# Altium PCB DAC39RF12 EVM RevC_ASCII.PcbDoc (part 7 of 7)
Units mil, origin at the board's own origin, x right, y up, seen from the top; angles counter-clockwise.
Board outline 5071.81 x 2716.54 mil, 16 copper layers (Top Layer, L2 GND1, L3 PWR1, L4 GND2, L5 PWR2, L6 GND3, L7 Ctrl Signal 1, L8 GND4, L9 GND5, L10 Ctrl Signal 2, L11 GND6, L12 PWR3, L13 GND7, L14 PWR4, L15 GND8, Bottom Layer), stack 82.4 mil thick; 596 components, 375 nets, 3310 pads, 1662 vias.
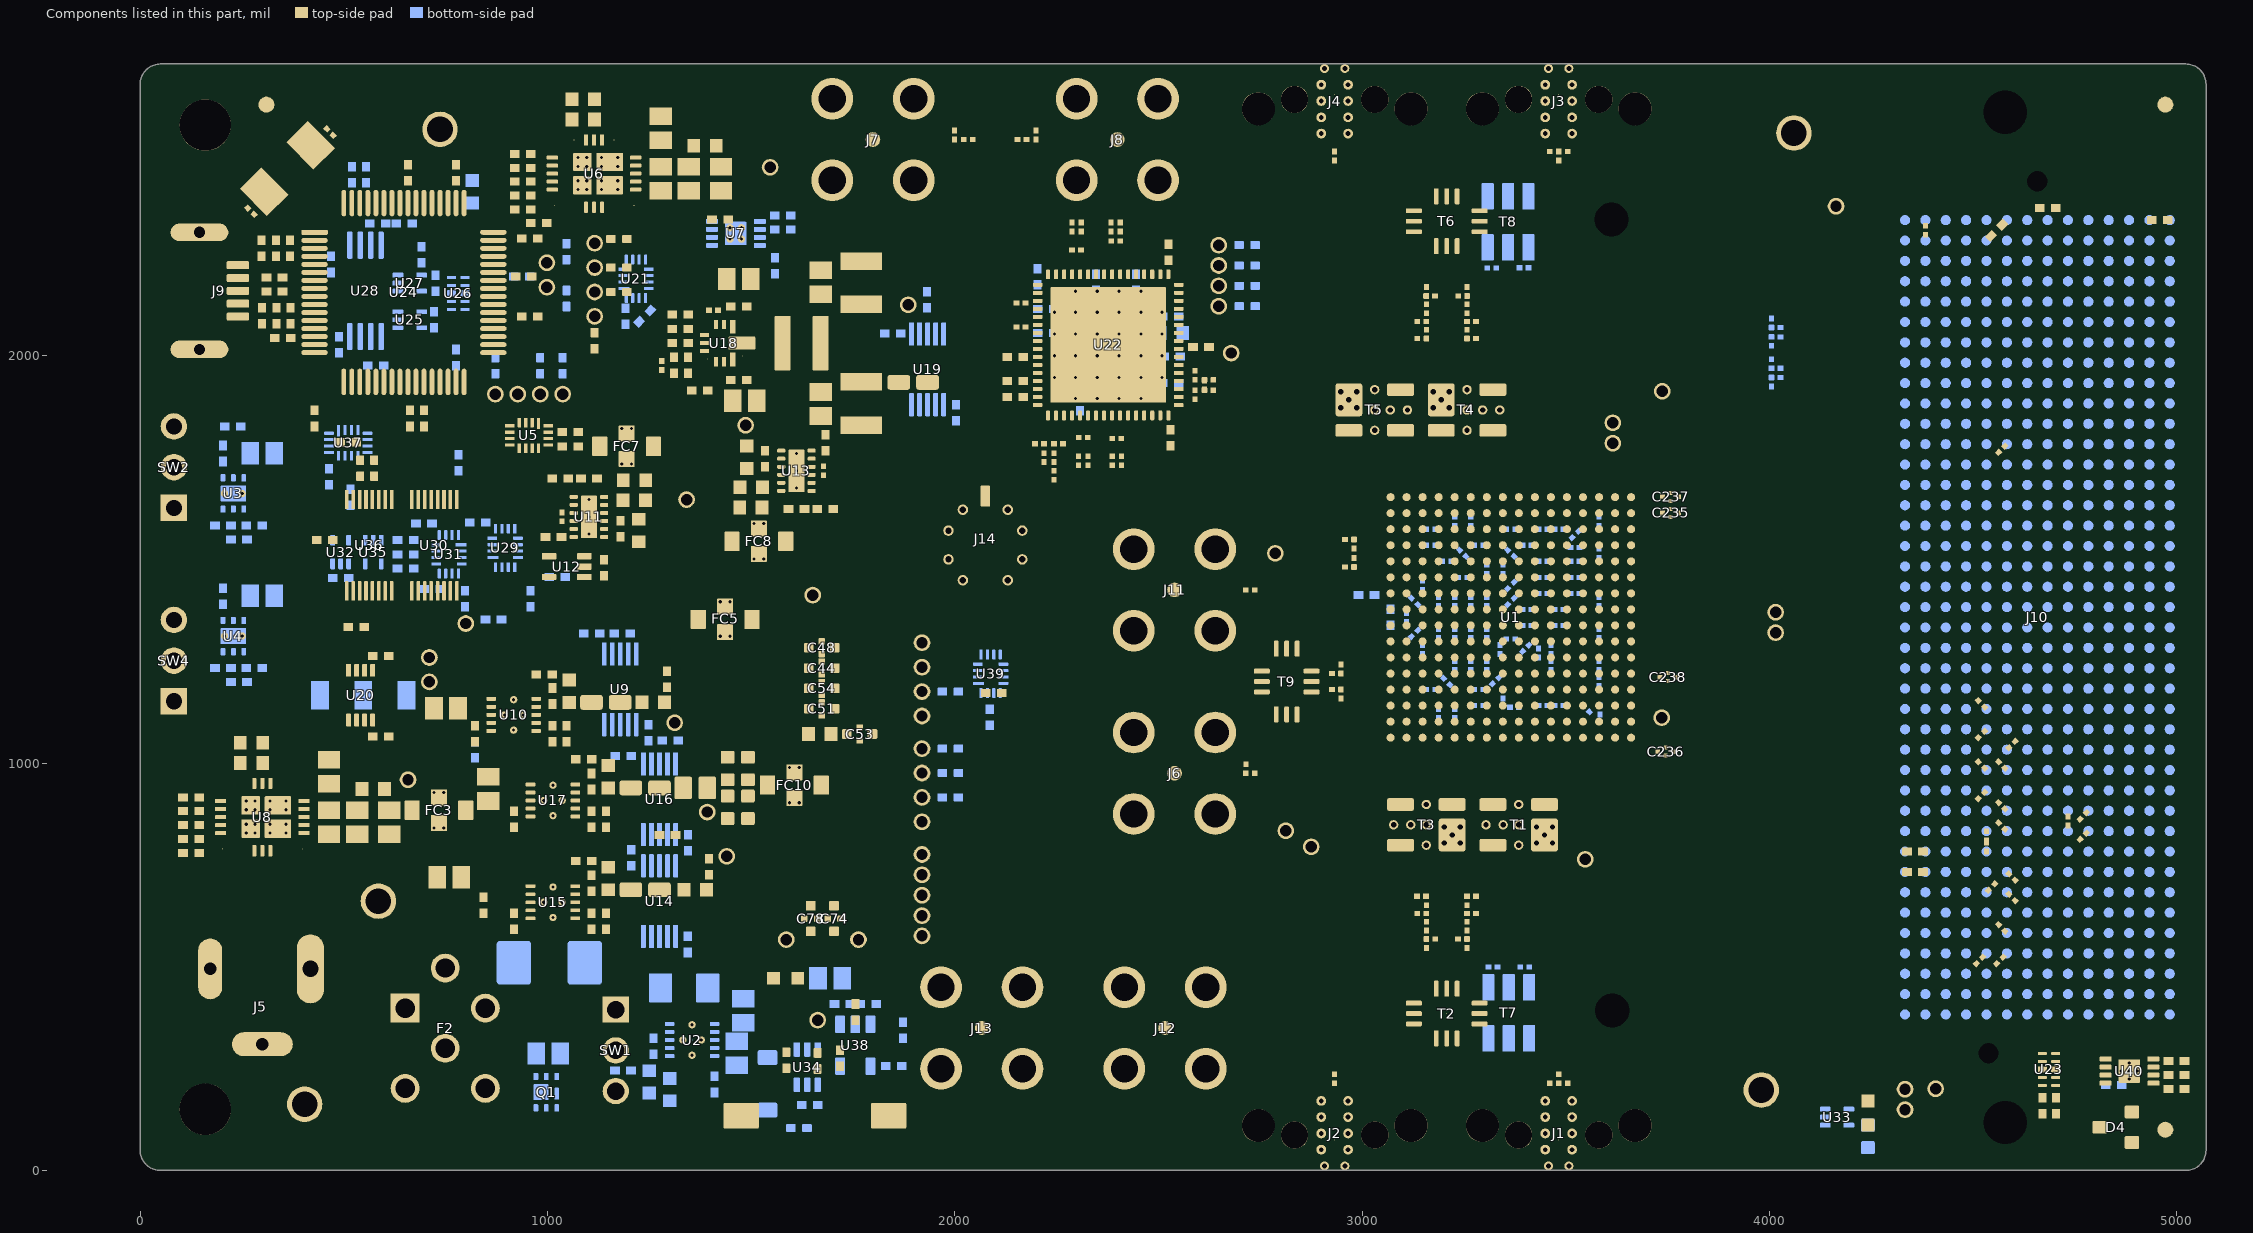
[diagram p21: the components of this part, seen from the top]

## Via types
v1: diameter 18, hole 8, Top Layer to Bottom Layer, tented both sides, 1558 vias
v2: diameter 20, hole 10, Top Layer to Bottom Layer, tented both sides, 92 vias
v3: diameter 27, hole 15, Top Layer to Bottom Layer, tented both sides, 12 vias

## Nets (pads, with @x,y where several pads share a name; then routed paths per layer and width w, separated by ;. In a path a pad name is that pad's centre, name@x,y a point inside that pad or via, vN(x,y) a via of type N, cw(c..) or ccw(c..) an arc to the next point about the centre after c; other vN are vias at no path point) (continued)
pads on no net: "U6. "@1016.37,2525.57 FID1.1 FID2.1 FID3.1 H3. H4. H5.1 H6.1 J6.5 J9.1 J9.4 J10. J10.A2 J10.A3 J10.A6 J10.A7 J10.A10 J10.A11 J10.A14 J10.A15 J10.A18 J10.A19 J10.B1 J10.B4 J10.B5 J10.B8 J10.B9 J10.B12 J10.B13 J10.B16 J10.B17 J10.B40 J10.C6 J10.C7 J10.C10 J10.C11 J10.C14 J10.C15 J10.C16 J10.C18 J10.C19 J10.D8 J10.D9 J10.D11 J10.D12 J10.D14 J10.D15 J10.D16 J10.D17 J10.D18 J10.D20 J10.D21 J10.D29 J10.D33 J10.D34 J10.E2 J10.E3 J10.E6 J10.E7 J10.E9 J10.E10 J10.E12 J10.E13 J10.E15 J10.E16 J10.E17 J10.E18 J10.E19 J10.E21 J10.E22 J10.E24 J10.E25 J10.E27 J10.E28 J10.E30 J10.E31 J10.E33 J10.E34 J10.E36 J10.E37 J10.F4 J10.F5 J10.F7 J10.F8 J10.F10 J10.F11 J10.F13 J10.F14 J10.F15 J10.F16 J10.F17 J10.F18 J10.F19 J10.F20 J10.F22 J10.F23 J10.F25 J10.F26 J10.F28 J10.F29 J10.F31 J10.F32 J10.F34 J10.F35 J10.F37 J10.F38 J10.G2 J10.G3 J10.G15 J10.G16 J10.G17 J10.G18 J10.G19 J10.G21 J10.G22 J10.G24 J10.G25 J10.H1 J10.H4 J10.H5 J10.H7 J10.H8 J10.H10 J10.H11 J10.H13 J10.H14 J10.H15 J10.H16 J10.H17 J10.H19 J10.H20 J10.H22 J10.H23 J10.H35 J10.J2 J10.J3 J10.J4 J10.J5 J10.J6 J10.J7 J10.J9 J10.J10 J10.J12 J10.J13 J10.J15 J10.J16 J10.J17 J10.J18 J10.J19 J10.J21 J10.J22 J10.J24 J10.J25 J10.J27 J10.J28 J10.J30 J10.J31 J10.J33 J10.J34 J10.J36 J10.J37 J10.J39 J10.K1 J10.K2 J10.K3 J10.K4 J10.K5 J10.K7 J10.K8 J10.K10 J10.K11 J10.K12 J10.K13 J10.K14 J10.K15 J10.K16 J10.K17 J10.K19 J10.K20 J10.K22 J10.K23 J10.K25 J10.K26 J10.K28 J10.K29 J10.K31 J10.K32 J10.K34 J10.K35 J10.K37 J10.K38 J10.K40 J10.L3 J10.L4 J10.L5 J10.L7 J10.L8 J10.L9 J10.L10 J10.L12 J10.L13 J10.L15 J10.L16 J10.L17 J10.L19 J10.L20 J10.L21 J10.L24 J10.L25 J10.L28 J10.L29 J10.M2 J10.M3 J10.M4 J10.M5 J10.M6 J10.M7 J10.M10 J10.M11 J10.M12 J10.M14 J10.M15 J10.M17 J10.M18 J10.M19 J10.M20 J10.M22 J10.M23 J10.M26 J10.M27 J10.M30 J10.M31 J10.M34 J10.M35 J10.M38 J10.M39 J10.Y2 J10.Y3 J10.Y10 J10.Y11 J10.Y14 J10.Y15 J10.Y34 J10.Y35 J10.Y38 J10.Y39 J10.Z4 J10.Z5 J10.Z12 J10.Z13 J10.Z16 J10.Z17 J10.Z20 J10.Z21 J10.Z32 J10.Z33 J10.Z36 J10.Z37 J11.5 J12.5 J13.5 LBL1.0 Q1.0 T1.4 T3.4 T4.4 T5.4 U2.9 U3.3 U3.7@211.25,1662.04 U3.7@246.68,1662.04 U4.3 U4.7@211.25,1312.04 U4.7@246.68,1312.04 U6.4 U8.4 U9.3 U11.2 U11.11 U12.1 U13.1 U13.2 U13.11 U14.3 U16.3 U19.3 U22.1 U22.2 U22.7 U22.8 U22.9 U22.13 U22.14 U22.15 U22.16 U22.22 U22.23 U22.29 U22.30 U22.31 U22.32 U22.40 U22.41 U22.43 U22.44 U22.46 U22.48 U22.49 U22.50 U22.59 U22.60 U22.61 U22.62 U22.63 U23.3@4669.81,247.98 U23.8@4702.69,247.98 U24.21 U24.22 U24.23 U24.24 U24.29 U24.30 U24.32 U24.33 U24.34 U24.36 U24.55 U24.57 U24.58 U24.59 U24.60 U26.3@764.51,2153.25 U26.8@797.38,2153.25 U28.6 U28.7 U29.4 U29.9 U39.4 U39.6 U39.9

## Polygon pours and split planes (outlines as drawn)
GND on L5 PWR2 "L5_PWR2_GND_P081" (solid, remove dead copper, pour order 81): 10,0 5071.81,0 5071.81,2716.54 10,2716.54
VDDLB on L5 PWR2 "L5 PWR2-VDDLB" (solid, remove dead copper, pour order 79): 1384.73,0 4571.81,0 4571.81,2327.76 3294.03,2327.76 3294.03,1360 3839.92,1360 3839.92,415 1681.3,415 1681.3,627.38 1384.73,627.38
VDDCLK10 on L5 PWR2 "L5 PWR2-VDDCLK10" (solid, pour order 44): 483.65,896.46 3179.62,896.46 3179.62,1132.95 3278.98,1232.32 3278.98,1484.8 3190.99,1572.79 3190.99,2329.24 483.65,2329.24
VDDLA on L5 PWR2 "L5_PWR2_VDDLA_P075" (solid, pour order 75): 1681.68,415 3839.92,415 3839.92,1349.14 3294.03,1349.14 3294.03,752.36 1681.68,752.36
GND on L10 Ctrl Signal 2 "L10_CTRL_SIGNAL_2_GND_P177" (solid, remove dead copper, pour order 177): 10,0 5071.81,0 5071.81,2716.54 10,2716.54
VDD_FPGA on L10 Ctrl Signal 2 "L10 Ctrl Signal 2-VDD_FPGA" (solid, pour order 168): 993.77,1760.42 1364.46,1760.42 1364.46,2262.22 1170.34,2262.22 1170.34,2077.47 1051.73,2077.47 1051.73,1858.95 993.77,1858.95
GND on L12 PWR3 "L12_PWR3_GND_P181" (solid, remove dead copper, pour order 181): 10,0 5071.81,0 5071.81,2716.54 10,2716.54
VADJ_FMC on L12 PWR3 "L12 PWR3-VADJ_FMC" (solid, pour order 173): 4718.81,0 4718.81,705.91 2091.18,705.91 2091.18,186.96 410,186.96 410,1210 0,1210 0,0 2091.18,0
VEExA on L12 PWR3 "L12 PWR3-VEExA" (solid, pour order 167): 1252.77,1628.99 2882.03,1628.99 2882.03,1931.86 3832.81,1931.86 3832.81,1219.99 3148.55,1219.99 3148.55,952.06 4571.81,952.06 4571.81,2716.54 2060,2716.54 2060,1845 1520.93,1845 1520.93,1956.81 1252.77,1956.81
VDDA18A on L12 PWR3 "L12 PWR3-VDDA18A" (solid, pour order 162): 1896.85,921.63 1896.85,706.97 3511.53,706.97 3511.53,950 3149.12,950 3147.55,1219.99 3832.81,1219.99 3832.81,1352.31 3041.46,1352.31 3041.46,1252.96 1681.23,1252.96 1681.23,921.63
VEExB on L12 PWR3 "L12 PWR3-VEExB" (solid, pour order 160): 1252.77,1432.97 2908.82,1432.97 2908.82,1477.87 3345.4,1477.87 3345.4,1613.69 1353.36,1613.69 1353.36,1685.58 1252.77,1685.58 1252.77,1491.34
VDDA18B on L12 PWR3 "L12 PWR3-VDDA18B" (solid, pour order 165): 1680.32,1252.96 3041.46,1252.96 3041.46,1352.31 3832.81,1352.31 3832.81,1931.86 2882.03,1931.86 2882.03,1613.69 3345.4,1613.69 3345.4,1477.87 2908.82,1477.87 2908.82,1401.04 1680.32,1401.04
VDDIO on L12 PWR3 "L12 PWR3-VDDIO" (solid, pour order 171): 410,186.96 2091.18,186.96 2091.18,479.32 1252.77,479.32 1252.77,1932 410,1932 410,1470.29 25.49,1470.52 25.49,1299.81 410,1299.81
VDD_FPGA on L12 PWR3 "L12 PWR3-VDD_FPGA" (solid, pour order 156): 27,1210 1020.86,1210 1020.86,1437.02 1075.46,1437.02 1075.46,1799.59 746.4,1799.59 746.4,1431.71 631.8,1431.71 631.8,1300.11 25.49,1300.11 27,1299.81
3p3V_Utility on L12 PWR3 "L12 PWR3-3p3V_Utility" (solid, remove dead copper, pour order 170): 10,1470.52 407.23,1470.52 407.23,1932 1106.71,1932 1252.77,1932 1252.77,1956.81 1520.93,1956.81 1520.93,1845 2057.94,1845 2057.94,2716.54 10,2716.54
3P3VAUX-FMC on L12 PWR3 "L12 PWR3-3P3VAUX-FMC" (solid, pour order 130): 4550,0 4678.13,0 4678.13,295 4865,295 4865,0 5071.81,0 5071.81,853.18 4505,853.18 4505,720 4720.81,720 4720.81,345 4550,345
3p3V_EEPROM on L12 PWR3 "L12_PWR3_3P3V_EEPROM_P133" (solid, pour order 133): 4678.13,295 4678.13,0 4865,0 4865,295 4860,295
GND on L3 PWR1 "L3_PWR1_GND_P175" (solid, remove dead copper, pour order 175): 10,0 5071.81,0 5071.81,2716.54 10,2716.54
3p3V_Clock on L3 PWR1 "L3 PWR1-3p3V_Clock" (solid, pour order 153): 1906.07,1790.96 3030.83,1790.96 3030.83,2716.54 1440.65,2716.54 1440.65,1923.45 1906.07,1923.45
DVDD on L3 PWR1 "L3 PWR1-DVDD" (solid, remove dead copper, pour order 137): 1440.65,359.67 5071.81,359.67 5071.81,2716.54 3030.83,2716.54 3030.83,1790.96 1896.85,1790.96 1896.85,1920.87 1440.65,1920.87
3p3V_Utility on L3 PWR1 "L3 PWR1-3p3V_Utility" (solid, pour order 120): 10,0 5071.81,0 5071.81,359.67 1440.2,359.67 1440.2,1262.21 1103.21,1262.21 1103.21,1435.28 1163.9,1435.28 1163.9,1912.63 10,1912.63
12V on L3 PWR1 "NONET_L10_P-001" (solid, pour order 30): 222.99,986.84 657.49,986.84 657.49,1240.02 222.99,1240.02 222.99,986.56
VDDIO on L3 PWR1 "NONET_L10_P-001" (solid, pour order 139): 1103.21,1435.28 1103.21,1262.21 1441.26,1262.21 1441.26,2210 1166.34,2210 1166.34,1435.28
VCORE on L3 PWR1 "NONET_L10_P-001" (solid, pour order 151): 433.62,2415.74 433.62,2041.74 889.65,2041.74 889.65,2415.74
GND on L2 GND1 "L2_GND1_GND_P028" (solid, remove dead copper, pour order 28): 0,0 5071.81,0 5071.81,2716.54 0,2716.54
GND on L14 PWR4 "L14_PWR4_GND_P157" (solid, remove dead copper, pour order 157): 10,0 5071.81,0 5071.81,2716.54 10,2716.54
12V_FMC on L14 PWR4 "L14 PWR4-12V_FMC" (solid, remove dead copper, pour order 145): 465.8,0 5071.81,0.82 5071.81,665 3787,665 3787,465 1590,465 1590,262.71 465.8,262.71
VDDIO on L14 PWR4 "L14 PWR4-VDDIO" (solid, pour order 132): 3447.76,739.03 3447.76,1241.53 2850.8,1241.53 2850.8,865 1680.2,865 1680.2,1412.75 1542.02,1412.75 1542.02,1334.94 1168.01,1334.94 1168.01,1437.02 1166.34,1437.02 1020.86,1437.02 1020.86,739.03
VDDCLK18 on L14 PWR4 "L14 PWR4-VDDCLK18" (solid, pour order 143): 3487.82,1047.89 3800,1047.89 3800,1160.81 3685,1160.81 3685,1365.43 2492.76,1365.43 2492.76,1029.34 1793.53,1029.34 1793.51,1030.82 1793.51,1162.48 1680.2,1162.48 1680.2,864.59 2850.32,864.59 2850.32,1241.53 3487.82,1241.53 3487.82,1144.71
VDDSYS18 on L14 PWR4 "L14_PWR4_VDDSYS18_P102" (solid, pour order 102): 3266.66,1365.43 3266.66,1546.64 1909.73,1546.64 1909.73,1142.11 1793.51,1142.11 1793.51,1030.82 2492.76,1030.82 2492.76,1365.43
VDDR on L14 PWR4 "L14_PWR4_VDDR_P116" (solid, pour order 116): 1909.73,1164.8 1909.73,1546.64 3266.66,1546.64 3266.66,1365.43 3882.81,1365.43 3882.81,1900.62 1680.2,1900.62 1680.2,1164.8
12V on L14 PWR4 "L14 PWR4-12V" (solid, pour order 123): 10,0 465.8,0 465.8,264.63 1590,264.63 1590,569.7 678.2,569.7 678.2,1808.29 1520.93,1808.29 1520.93,2295.21 1107.23,2295.21 1107.23,2396.66 848.92,2396.66 848.92,2551.45 1108.69,2551.45 1108.69,2716.54 10,2716.54
fanPwr on L14 PWR4 "L14 PWR4-fanPwr" (solid, pour order 101): 1701.5,528 3718.17,528 3718.17,804.72 4062.49,804.72 4062.49,1365.43 3718.17,1365.43 3718.17,1248.06 3841.46,1248.06 3841.46,956.91 3553.55,956.91 3553.55,724.33 934.37,724.33 934.37,1227.31 496.42,1227.31 496.42,1075.78 756.51,1075.78 756.51,603.37 1701.5,603.37
3p3V_Clock on L14 PWR4 "NONET_L10_P-001" (solid, pour order 129): 1225.36,1560.77 1683.75,1560.77 1683.75,2716.54 1108.69,2716.54 1108.69,2551.45 848.92,2551.45 848.92,2396.66 1107.23,2396.66 1107.23,2295.21 1520.93,2295.21 1520.93,1808.29 1225.36,1808.29
GND on L4 GND2 "L4_GND2_GND_P043" (solid, remove dead copper, pour order 43): 10,0 5071.81,0 5071.81,2716.54 10,2716.54
GND on L7 Ctrl Signal 1 "L7_CTRL_SIGNAL_1_GND_P182" (solid, remove dead copper, pour order 182): 10,0 5071.81,0 5071.81,2716.54 10,2716.54
VDD_FPGA on L7 Ctrl Signal 1 "gnd" (solid, pour order 154): 1310,1850 2130.12,1850 2130.12,1158.43 1784.05,1158.43 1784.05,1598.91 1310,1598.91
VDDIO on L7 Ctrl Signal 1 "gnd" (solid, pour order 178): 2130.12,1158.43 2130.12,1065 1580,1065 1580,1460 1785,1460 1785,1160 2130,1160
GND on L6 GND3 "L6_GND3_GND_P045" (solid, remove dead copper, pour order 45): 10,0 5071.81,0 5071.81,2716.54 10,2716.54
GND on L8 GND4 "L8_GND4_GND_P048" (solid, remove dead copper, pour order 48): 10,0 5071.81,0 5071.81,2716.54 10,2716.54
GND on L9 GND5 "L9_GND5_GND_P049" (solid, remove dead copper, pour order 49): 10,0 5071.81,0 5071.81,2716.54 10,2716.54
GND on L11 GND6 "L11_GND6_GND_P051" (solid, remove dead copper, pour order 51): 10,0 5071.81,0 5071.81,2716.54 10,2716.54
GND on L13 GND7 "L13_GND7_GND_P053" (solid, remove dead copper, pour order 53): 10,0 5071.81,0 5071.81,2716.54 10,2716.54
GND on L15 GND8 "L15_GND8_GND_P054" (solid, remove dead copper, pour order 54): 10,0 5071.81,0 5071.81,2716.54 10,2716.54
GND on Bottom Layer "BOTTOM_LAYER_GND_P158" (solid, remove dead copper, pour order 158): 10,0 5071.81,0 5071.81,2716.54 10,2716.54
GND on Top Layer "TOP_LAYER_GND_P183" (solid, remove dead copper, pour order 183): 0,0 5071.81,0 5071.81,2716.54 0,2716.54

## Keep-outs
Keep-Out Layer:
  text ".Layer_Name" at 587,-858.49 h60

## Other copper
Top Layer:
  text ".Layer_Name" at 579.82,-843.49 h60
L2 GND1:
  text ".Layer_Name" at 579.82,-843.49 h60
L3 PWR1:
  text ".Layer_Name" at 579.82,-843.49 h60
L4 GND2:
  text ".Layer_Name" at 579.82,-843.49 h60
L5 PWR2:
  text "PWR2" at 579.82,-843.49 h60
L6 GND3:
  text ".Layer_Name" at 579.82,-843.49 h60
L11 GND6:
  text ".Layer_Name" at 579.82,-843.49 h60
L12 PWR3:
  text ".Layer_Name" at 579.82,-843.49 h60
L13 GND7:
  text ".Layer_Name" at 579.82,-843.49 h60
L14 PWR4:
  text ".Layer_Name" at 579.82,-843.49 h60
L15 GND8:
  text ".Layer_Name" at 579.82,-843.49 h60
L7 Ctrl Signal 1:
  text ".Layer_Name" at 579.82,-843.49 h60
L10 Ctrl Signal 2:
  text ".Layer_Name" at 579.82,-843.49 h60
L8 GND4:
  text ".Layer_Name" at 579.82,-843.49 h60
L9 GND5:
  text ".Layer_Name" at 579.82,-843.49 h60
Bottom Layer:
  text ".Layer_Name" at 579.82,-843.49 h60

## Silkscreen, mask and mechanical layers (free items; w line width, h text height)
Top Overlay:
  lines w5: 145,2335 255,2335 280,2310 ; 260,2310 280,2310 ; 639.26,1177.37 639.26,1287.11 ; 280,2310 280,2330 280,2310 ; 25,2335 150,2335 150,2450 25,2450 25,2335
  lines w7: 1505,220 1505,410 ; 1695,345 1695,490 ; 1953.61,1143.1 2005.97,1143.16 ; 1954.4,881.95 2006.76,882.01 ; 2069.92,597.86 2123.63,597.97 ; 2071.27,797.97 2123.63,798.03 ; 2540.71,984.9 2540.71,1034.9 ; 2683.86,2298.35 2733.86,2298.35
  text "LMK" at 2614,2161 h30 r90
  text "DAC39RF12EVM / RevC   DC296" at 3791.14,1855.95 h60
  text "SYNC" at 678.53,1175.95 h30 r90
  text "USB2FMC" at 1889,1111 h30 r90
  text "DAC SPI" at 1889,851 h30 r90
  text "FMC SPI" at 1889,571 h30 r90
  text ".Layer_Name" at 579.82,-843.49 h60
Bottom Overlay:
  lines w7: 895,1835 895,1885 ; 1535,430 1672.65,431.76 ; 1830,1140 1880,1140 ; 1840,880 1890,880 ; 1950,600 2000,600 ; 1950,800 2000,800 ; 2050,1141.48 2100,1141.48 ; 2570,2295 2620,2295 ; 2585,1095 2585,1145 ; 2845,965 2845,1015 ; 3095,1325 3115,1325 3145,1355 3605,1355 3645,1355 ; 3105,1325 3090,1325 ; 3090,1325 3090,995 3015,920 3015,620 3465,620 3495,620 3500,620 3500,510 3645,510 3645,1355 ; 3090,1325 3090,1625 2985,1625 2985,2082.06 3645,2082.06 3645,1355
  text "DAC" at 1756,886 h30 r270
  text "LMX" at 2899,876 h30
  text "FMC" at 1851,641 h30 r270
  text ".Layer_Name" at 587,-858.49 h60
Top Paste:
  text ".Layer_Name" at 587,-858.49 h60
Bottom Paste:
  text ".Layer_Name" at 593.41,-871.99 h60
Top Solder:
  text ".Layer_Name" at 587,-858.49 h60
  text ".Layer_Name" at 587,-858.49 h60
Bottom Solder:
  rectangle: 2967.44,1192.08 2975.94,1208.5
  text ".Layer_Name" at 593.41,-871.99 h60
Drill Guide:
  text ".Layer_Name" at 417,-408.49 h60
M1 Board Outline:
  lines w10: 0,50 ccw(c50,50) 50,0 110,0 4970,0 5021.81,0 ccw(c5021.81,50) 5071.81,50 5071.81,100 5071.81,2616.53 5071.81,2666.54 ccw(c5021.81,2666.54) 5021.81,2716.54 4970,2716.54 100,2716.54 50,2716.54 ccw(c50,2666.54) 0,2666.54 0,2616.53 0,100 0,50
  text ".Layer_Name" at 587,-858.49 h60
M2 Board Dimensions:
  rectangle: 135,-400 510,-275
  rectangle: 10,-275 135,-150
  lines w7: 10,-275 1010,-275 ; 10,-150 10,-400 1010,-400 1010,-150 ; 135,-400 135,-150 ; 260,-400 260,-150 ; 510,-400 510,-150 ; 760,-400 760,-150
  text ".Layer_Name" at 587,-858.49 h60
M3 3D STEP Top:
  text ".Layer_Name" at 587,-858.49 h60
M4 3D STEP Bottom:
  text ".Layer_Name" at 593.41,-871.99 h60
M5 Assembly Top:
  lines w10: -282,-930.17 6318,-930.17 ; -282,-726.83 6320,-726.83 ; -282,-523.5 -282,-1133.5 3723,-1133.5 6320,-1133.5 6320,-523.5 -281.5,-523.5 -281.5,-1133.5 1294,-1133.5 ; 2183,-1133.5 2183,-523.5 ; 3450,-726.83 3450,-523.5 ; 4290,-726.83 4290,-523.5 ; 4912,-1140 4912,-937.17
  text "COMPONENTS MARKED 'DNP' SHOULD NOT BE POPULATED." at 1163.5,-318.5 h60
  text "ASSEMBLY VARIANT:" at 1163,-434 h60
  text ".VariantName" at 2199,-434 h60
  text "PCB VIEWED FROM TOP SIDE" at -218.5,-655.67 h60
  text "BOARD #:" at 2258,-655.67 h60
  text ".PRJ_Number" at 2803.5,-655.67 h60
  text "REV:" at 3648,-655.67 h60
  text ".PCB_Rev" at 3939.5,-655.67 h60
  text "SVN REV:" at 4486,-655.67 h60
  text ".VersionControl_RevNumber" at 4992,-655.67 h60
  text "PLOT NAME =" at -218.5,-1064.34 h60
  text ".plot_File_Name" at 587,-1064.34 h60
  text "GENERATED    :" at 2260,-1064.34 h60
  text ".Print_Date" at 3129.5,-1064.34 h60
  text ".Print_Time" at 3858.5,-1064.34 h60
  text "TEXAS INSTRUMENTS" at 5123,-1064.34 h60
M6 Assembly Bottom:
  lines w10: -282.5,-727.33 6319.5,-727.33 ; -280.5,-930.67 6319.5,-930.67 ; 1125.5,-1140.5 1125.5,-937.67 ; 1747.5,-727.33 1747.5,-524 ; 2587.5,-727.33 2587.5,-524 ; 3854.5,-1134 3854.5,-524 ; 4743.5,-1134 6319,-1134 6319,-524 -282.5,-524 -282.5,-1134 2314.5,-1134 6319.5,-1134 6319.5,-524
  text "COMPONENTS MARKED 'DNP' SHOULD NOT BE POPULATED." at 6112,-318 h60
  text ".VariantName" at 5068,-434 h60
  text "ASSEMBLY VARIANT:" at 6107,-434 h60
  text ".VersionControl_RevNumber" at 1045.5,-656.17 h60
  text "SVN REV:" at 1551.5,-656.17 h60
  text ".PCB_Rev" at 2098,-656.17 h60
  text "REV:" at 2389.5,-656.17 h60
  text ".PRJ_Number" at 3234,-656.17 h60
  text "BOARD #:" at 3779.5,-656.17 h60
  text "PCB VIEWED FROM BOTTOM SIDE" at 6256,-656.17 h60
  text "TEXAS INSTRUMENTS" at 914.5,-1064.84 h60
  text ".Print_Time" at 2179,-1064.84 h60
  text ".Print_Date" at 2908,-1064.84 h60
  text "GENERATED    :" at 3777.5,-1064.84 h60
  text ".plot_File_Name" at 5450.5,-1064.84 h60
  text "PLOT NAME =" at 6256,-1064.84 h60
M9 Title Sheet:
  lines w10: -583,2316.39 -283,2316.39 ; -583,6066.39 -283,6066.39 ; -583,9816.39 -283,9816.39 ; 2752,-1433.61 2752,-1133.61 ; 2752,13266.39 2752,13566.39 ; 6082,-1433.61 6082,-1133.61 ; 6082,13266.39 6082,13566.39 ; 9417,-1433.61 9417,-1133.61 ; 9417,13266.39 9417,13566.39 ; 11130.5,-1142.61 11130.5,-532.61 16113,-532.61 ; 12747,-1433.61 12747,-1133.61 ; 12747,13266.39 12747,13566.39 ; 16082,-1433.61 16082,-1133.61 ; 16082,13266.39 16082,13566.39 ; 16113,-1142.61 16113,-532.61 ; 16113,-832.61 19113,-832.61 ; 16113,-232.61 19113,-232.61 ; 16114,361.39 19114,361.39 ; 17618,-1132.61 17618,-532.61 ; 19113,-532.61 16113,-532.61 ; 19113,67.39 16113,67.39 ; 19117,2119.54 19417,2119.54 ; 19117,5869.54 19417,5869.54 ; 19117,9816.39 19417,9816.39 ; 19118,861.89 16114,861.89 16113,861.89 16113,361.39 16113,67.39 ; 16113,-532.61 16113,67.39 ; -583,-1433.61 -583,13566.39 19417,13566.39 19417,-1433.61 -583,-1433.61 ; -283,-1133.61 -283,13266.39 19117,13266.39 19117,-1133.61 -283,-1133.61
  text "1" at 1068.34,13381.39 h70
  text "2" at 4394,13381.39 h70
  text "3" at 7724,13381.39 h70
  text "4" at 11059,13381.39 h70
  text "5" at 14384,13381.39 h70
  text "6" at 17719,13381.39 h70
  text "A" at -453,11603.39 h70
  text "A" at 19247,11603.39 h70
  text "B" at -453,7853.39 h70
  text "B" at 19247,7853.39 h70
  text "C" at -453,4103.39 h70
  text "C" at 19247,3906.54 h70
  text "D" at -453,353.39 h70
  text "D" at 19247,353.39 h70
  text "PROJECT TITLE:" at 16153,268.39 h45
  text ".PRJ_Title" at 16203,135.06 h70
  text "DESIGNED FOR:" at 16153,-32.61 h45
  text ".PRJ_Customer" at 16203,-172.61 h70
  text "FILE NAME:" at 16153,-332.61 h45
  text ".PCB_File_Name_No_Path" at 16203,-452.61 h70
  text "Texas Instruments (TI) and/or its licensors do not warrant the accuracy or completeness of this specification" at 11183.5,-614.45 h45
  text "ENGINEER:" at 16153,-622.61 h45
  text "LAYOUT BY:" at 17658,-622.61 h45
  text "or any information contained therein. TI and/or its licensors do not warrant that this design will meet" at 11138.51,-727.11 h45
  text ".PRJ_Engineer" at 16203,-777.6 h70
  text ".PCB_Layout" at 17708.5,-777.6 h70
  text "the specifications, will be suitable for your application or fit for any particular purpose, or will operate in" at 11138.51,-839.78 h45
  text ".Layer_Name" at 587,-858.49 h60
  text "ALTIUM DESIGNER VERSION:" at 17658,-932.61 h45
  text "an implementation. TI and/or its licensors do not warrant that the design is production worthy. You should" at 11138.51,-952.44 h45
  text "completely validate and test your design implementation to confirm the system functionality for your application." at 11183.5,-1065.11 h45
  text ".print_Scale" at 16203,-1065.94 h70
  text ".Application_BuildNumber" at 17708.5,-1065.94 h70
  text "1" at 1068.34,-1318.61 h70
  text "2" at 4394,-1318.61 h70
  text "3" at 7724,-1318.61 h70
  text "4" at 11059,-1318.61 h70
  text "5" at 14384,-1318.61 h70
  text "6" at 17719,-1318.61 h70
M10 Fab Notes:
  drawing of 213 lines, arcs and shapes, not listed
  text "M10 Fab Notes" at 16109.69,8057.1 h60
  text "DESIGN INFORMATION" at 17188.02,7939.98 h60
  text "MIN. TRACK WIDTH:" at 16543.46,7807.85 h60
  text "4" at 17639.7,7807.85 h60
  text "MIL" at 17794.46,7807.85 h60
  text "MIN. CLEARANCE:" at 16543.46,7683.73 h60
  text "MIL" at 17794.46,7683.73 h60
  text "3.5" at 17585,7675 h60
  text "MIN. VIA PAD SIZE:" at 16543.46,7559.6 h60
  text "18" at 17609.71,7559.6 h60
  text "MIL" at 17794.46,7559.6 h60
  text "0.05mm (2MIL)" at 17238.46,7429.7 h60
  text "MINIMUM ANNULAR RING" at 16214.23,7421.48 h60
  text "EXTERNAL" at 17946.46,7421.48 h60
  text "PER" at 16414.23,7311.35 h60
  text "IPC-D-275 CLASS 2 LEVEL C" at 16634.23,7311.35 h60
  text "MIL, HOLES" at 18122.46,7210.87 h60
  text "+/-" at 17730,7202.29 h60
  text "+/-" at 18584,7202.29 h60
  text "REGISTRATION TOLERANCES:" at 16214.23,7201.22 h60
  text "METAL" at 17414,7201.22 h60
  text "5" at 17990.2,7201.22 h60
  text "3" at 18823.2,7201.22 h60
  text "MIL" at 18939.46,7201.22 h60
  text "HOLE SIZE TOLERANCE (UNLESS OTHERWISE SPECIFIED):" at 16214.23,7102.91 h60
  text "+/-" at 18584,7100.03 h60
  text "3" at 18823.2,7098.97 h60
  text "MIL" at 18939.46,7098.97 h60
  text "MATERIAL:" at 16139.46,6961.32 h60
  text "ISOLA FR4-370HR (or Equivalent)" at 17125.9,6832.8 h60
  text "X" at 16981.46,6824.81 h60
  text "FR-408" at 16560.46,6819.15 h60
  text "Isola I-Speed" at 17125.9,6635.95 h60
  text "Meg4" at 16560.46,6623.44 h60
  text "X" at 16425.9,6440.64 h60
  text "Meg6 (or Equivalent)" at 16560.46,6426.59 h60
  text "OTHER" at 16600.46,6229.74 h60
  text "62 MIL (1.6mm) +/-10%" at 16880.56,6086.71 h60
  text "81 MIL  +/-10%" at 18456.53,6086.71 h60
  text "X" at 18050.7,6082.23 h60
  text "THICKNESS:" at 16214.23,6078.49 h60
  text "OTHER" at 18165.46,6078.49 h60
  text "TOLERANCE:" at 16214.23,5940.17 h60
  text "X" at 17062.46,5940.17 h60
  text "ANSI IPC-6012 TYPE 3 CLASS 2" at 17240.48,5940.17 h60
  text "OTHER +/-" at 17240.46,5795.99 h60
  text "BOW & TWIST:" at 16214.23,5650.8 h60
  text "X" at 17062.46,5650.8 h60
  text "ANSI IPC-6012 TYPE 3 CLASS 2" at 17240.48,5650.8 h60
  text "OTHER +/-" at 17240.46,5504.1 h60
  text "DRILLING:" at 16139.46,5373.48 h60
  text "NC_DRILL FILES" at 17900.46,5268.29 h60
  text "REFERENCE:" at 16214.23,5264.36 h60
  text "X" at 16871.46,5264.26 h60
  text "AS SHOWN" at 17049.46,5264.36 h60
  text "X" at 17772.46,5264.36 h60
  text "OTHER" at 18198.46,5122.1 h60
  text "PTH COPPER THICKNESS:" at 16213.91,5118.57 h60
  text "X" at 17353.14,5118.57 h60
  text "20-30 um" at 17481.14,5118.57 h60
  text "BOARD FINISH:" at 16139.46,4970.98 h60
  text "SILKSCREEN:" at 16294.68,4860.85 h60
  text "X" at 17252.46,4860.85 h60
  text "TOP" at 17369.46,4860.85 h60
  text "X" at 17762.46,4860.85 h60
  text "BOTTOM" at 17880.46,4860.85 h60
  text "X" at 17762.71,4709.61 h60
  text "WHITE" at 18237.99,4706.26 h60
  text "SILKSCREEN COLOR:" at 16294.68,4705.66 h60
  text "WHITE" at 17369.46,4705.66 h60
  text "OTHER" at 17880.46,4705.66 h60
  text "RED" at 18486.25,4568.34 h60
  text "X" at 17975.14,4565.63 h60
  text "GREEN" at 17500.46,4562.21 h60
  text "OTHER" at 18118.46,4562.21 h60
  text "SOLDER RESIST COLOR:" at 16294.68,4555.35 h60
  text "X" at 17382.46,4407.96 h60
  text "MATTE" at 17500.46,4407.96 h60
  text "SEMI-GLOSS" at 18118,4407.32 h60
  text "IMMERSION GOLD (ENIG)" at 17200.46,4235.19 h60
  text "ENEPIG" at 18538,4227.97 h60
  text "SURFACE FINISH:" at 16139.46,4226.97 h60
  text "X" at 17022.46,4226.97 h60
  text "IMM. TIN/SILVER OR EQUIV" at 16469,4089.65 h60
  text "HARD GOLD (30u)" at 17900.46,4085.72 h60
  text "OTHER" at 16494,3888.87 h60
  text "X" at 17015,3735 h60
  text "ARRAY/PANEL:" at 16139.46,3733.49 h60
  text "CUT AND TRIM PER M1 BOARD OUTLINE" at 17200.46,3725.27 h60
  text "N.C. ROUTE" at 17200.46,3589.3 h60
  text "V. SCORE" at 18066.46,3589.3 h60
  text "CERTIFICATION:" at 16139.46,3460.17 h60
  text "MATERIALS AND WORKMANSHIP FOR ALL PCBS" at 16864.46,3460.17 h60
  text "TO MEET OR EXCEED THE REQUIREMENTS OF:" at 16864.46,3366.11 h60
  text "X" at 16501.97,3237.48 h60
  text "ANSI IPC-A-600F CLASS ->" at 16629.96,3237.48 h60
  text "X" at 18277.97,3237.48 h60
  text "2" at 18387.96,3237.48 h60
  text "1" at 18072.96,3235.98 h60
  text "3" at 18741.96,3235.98 h60
  text "X" at 17313.97,3089.8 h60
  text "RoHS" at 17441.96,3089.8 h60
  text "OTHER" at 18086.36,3089.8 h60
  text "PER ORDER" at 18483.42,3089.8 h60
  text "ALL BOARDS MUST MEET OR EXCEED UL94-V0 REQUIREMENTS." at 16167,2935.97 h60
  text "PCB MUST BEAR THE UL94V-0 UL REGISTERED MATERIAL ID NUMBER" at 16167,2819.91 h60
  text "ADDITIONAL REQUIREMENTS:" at 16139.46,2650.48 h60
  text "MICROSECTION:" at 16214.23,2543.36 h60
  text "YES" at 17119.96,2543.36 h60
  text "REQUIRED" at 17981.46,2399.02 h60
  text "BARE BOARD ELEC. TEST:" at 16214.23,2396.17 h60
  text "NONE" at 17519.96,2396.17 h60
  text "X" at 17863.46,2396.17 h60
  text "PER ORDER" at 18573.46,2396.17 h60
  text "X" at 16255.08,2205.71 h60
  text "16 MIL & SMALLER VIAS REQUIRE NON-CONDUCTIVE FILL AND PLANARIZE" at 16366.3,2115.16 h59
  text "X" at 16262.07,2010.12 h60
  text "OUTER LAYER TRACKS 12.3 MIL WIDE REQUIRE 50 OHM SINGLE-ENDED IMPEDANCE" at 16369.25,1904.53 h60
  text "X" at 16260.36,1803.37 h60
  text "OUTER LAYER TRACKS 6.25 MIL WIDE WITH 3.5 MIL AIR GAP REQUIRE 100 OHM DIFFERENTIAL IMPEDANCE" at 16369.25,1699.8 h60
  text "INNER LAYER XX & XX TRACKS XX MIL WIDE REQUIRE 50 OHM SINGLE-ENDED IMPEDANCE" at 16369.25,1495.08 h60
  text "X" at 16255.36,1393.37 h60
  text "INNER LAYER 10 TRACKS 4 MIL WIDE WITH   / 5 MIL AIR GAP REQUIRE 100 OHM DIFFERENTIAL IMPEDANCE" at 16355,1220 h60
  text "X" at 16255.36,1098.37 h60
  text "EDGE CONNECTORS AND GND ON LAYER BELOW MUST BE PULLED TO EDGE OF THE BOARD, NO PULL-BACK." at 16355,995 h60
  text ".Layer_Name" at 587,-858.49 h60
M11 Gerber Information:
  lines w10: -282,-930.17 6318,-930.17 ; -282,-726.83 6320,-726.83 ; -282,-523.5 -282,-1133.5 3723,-1133.5 6320,-1133.5 6320,-523.5 -281.5,-523.5 -281.5,-1133.5 1294,-1133.5 ; 2183,-1133.5 2183,-523.5 ; 3450,-726.83 3450,-523.5 ; 4290,-726.83 4290,-523.5 ; 4912,-1140 4912,-937.17
  text "ALL ARTWORK VIEWED FROM TOP SIDE" at -218.5,-655.67 h60
  text "BOARD #:" at 2258,-655.67 h60
  text ".PRJ_Number" at 2803.5,-655.67 h60
  text "REV:" at 3648,-655.67 h60
  text ".PCB_Rev" at 3939.5,-655.67 h60
  text "SVN REV:" at 4486,-655.67 h60
  text ".VersionControl_RevNumber" at 4992,-655.67 h60
  text "LAYER NAME =" at -218.5,-858.49 h60
  text "PLOT NAME =" at -218.5,-1064.34 h60
  text ".plot_File_Name" at 587,-1064.34 h60
  text "GENERATED    :" at 2260,-1064.34 h60
  text ".Print_Date" at 3129.5,-1064.34 h60
  text ".Print_Time" at 3858.5,-1064.34 h60
  text "TEXAS INSTRUMENTS" at 5123,-1064.34 h60
M12 Stackup:
  drawing of 971 lines, arcs and shapes, not listed
  text "Layer" at 5660.12,8592.65 h60
  text "Name" at 6070.03,8592.65 h60
  text "Material" at 7159.73,8592.65 h60
  text "Thickness" at 8019.49,8592.65 h60
  text "Constant" at 8669.33,8592.65 h60
  text "Board Layer Stack" at 9239.19,8592.65 h60
  text "Top Overlay" at 6070.03,8472.65 h60
  text "Top Solder" at 6070.03,8352.65 h60
  text "Solder Resist" at 7159.73,8352.65 h60
  text "0.40mil" at 8019.49,8352.65 h60
  text "3.5" at 8669.33,8352.65 h60
  text "1" at 5660.12,8232.65 h60
  text "Top Layer" at 6070.03,8232.65 h60
  text "1.40mil" at 8019.49,8232.65 h60
  text "Dielectric 1" at 6070.03,8112.65 h60
  text "Itera-mt40" at 7159.73,8112.65 h60
  text "6.00mil" at 8019.49,8112.65 h60
  text "3.33" at 8669.33,8112.65 h60
  text "2" at 5660.12,7992.65 h60
  text "L2 GND1" at 6070.03,7992.65 h60
  text "CF-004" at 7159.73,7992.65 h60
  text "1.40mil" at 8019.49,7992.65 h60
  text "Dielectric 2" at 6070.03,7872.65 h60
  text "FR4-370HR" at 7159.73,7872.65 h60
  text "3.00mil" at 8019.49,7872.65 h60
  text "3.72" at 8669.33,7872.65 h60
  text "3" at 5660.12,7752.65 h60
  text "L3 PWR1" at 6070.03,7752.65 h60
  text "CF-004" at 7159.73,7752.65 h60
  text "1.40mil" at 8019.49,7752.65 h60
  text "Dielectric 3" at 6070.03,7632.65 h60
  text "FR4-370HR" at 7159.73,7632.65 h60
  text "3.00mil" at 8019.49,7632.65 h60
  text "3.72" at 8669.33,7632.65 h60
  text "4" at 5660.12,7512.65 h60
  text "L4 GND2" at 6070.03,7512.65 h60
  text "CF-004" at 7159.73,7512.65 h60
  text "1.40mil" at 8019.49,7512.65 h60
  text "Dielectric 4" at 6070.03,7392.65 h60
  text "FR4-370HR" at 7159.73,7392.65 h60
  text "3.00mil" at 8019.49,7392.65 h60
  text "3.86" at 8669.33,7392.65 h60
  text "5" at 5660.12,7272.65 h60
  text "L5 PWR2" at 6070.03,7272.65 h60
  text "CF-004" at 7159.73,7272.65 h60
  text "1.40mil" at 8019.49,7272.65 h60
  text "Dielectric 5" at 6070.03,7152.65 h60
  text "FR4-370HR" at 7159.73,7152.65 h60
  text "3.00mil" at 8019.49,7152.65 h60
  text "3.72" at 8669.33,7152.65 h60
  text "6" at 5660.12,7032.65 h60
  text "L6 GND3" at 6070.03,7032.65 h60
  text "CF-004" at 7159.73,7032.65 h60
  text "1.40mil" at 8019.49,7032.65 h60
  text "Dielectric 6" at 6070.03,6912.65 h60
  text "FR4-370HR" at 7159.73,6912.65 h60
  text "3.00mil" at 8019.49,6912.65 h60
  text "3.86" at 8669.33,6912.65 h60
  text "7" at 5660.12,6792.65 h60
  text "L7 Ctrl Signal 1" at 6070.03,6792.65 h60
  text "CF-004" at 7159.73,6792.65 h60
  text "1.40mil" at 8019.49,6792.65 h60
  text "Dielectric 8" at 6070.03,6672.65 h60
  text "FR4-370HR" at 7159.73,6672.65 h60
  text "3.00mil" at 8019.49,6672.65 h60
  text "3.72" at 8669.33,6672.65 h60
  text "Dielectric 7" at 6070.03,6552.65 h60
  text "FR4-370HR" at 7159.73,6552.65 h60
  text "3.00mil" at 8019.49,6552.65 h60
  text "3.72" at 8669.33,6552.65 h60
  text "8" at 5660.12,6432.65 h60
  text "L8 GND4" at 6070.03,6432.65 h60
  text "CF-004" at 7159.73,6432.65 h60
  text "1.40mil" at 8019.49,6432.65 h60
  text "Dielectric 9" at 6070.03,6312.65 h60
  text "FR4-370HR" at 7159.73,6312.65 h60
  text "6.00mil" at 8019.49,6312.65 h60
  text "3.86" at 8669.33,6312.65 h60
  text "9" at 5660.12,6192.65 h60
  text "L9 GND5" at 6070.03,6192.65 h60
  text "CF-004" at 7159.73,6192.65 h60
  text "1.40mil" at 8019.49,6192.65 h60
  text "Dielectric 11" at 6070.03,6072.65 h60
  text "FR4-370HR" at 7159.73,6072.65 h60
  text "3.00mil" at 8019.49,6072.65 h60
  text "3.72" at 8669.33,6072.65 h60
  text "Dielectric 10" at 6070.03,5952.65 h60
  text "FR4-370HR" at 7159.73,5952.65 h60
  text "3.00mil" at 8019.49,5952.65 h60
  text "3.72" at 8669.33,5952.65 h60
  text "10" at 5660.12,5832.65 h60
  text "L10 Ctrl Signal 2" at 6070.03,5832.65 h60
  text "CF-004" at 7159.73,5832.65 h60
  text "1.40mil" at 8019.49,5832.65 h60
  text "Dielectric 12" at 6070.03,5712.65 h60
  text "FR4-370HR" at 7159.73,5712.65 h60
  text "3.00mil" at 8019.49,5712.65 h60
  text "3.86" at 8669.33,5712.65 h60
  text "11" at 5660.12,5592.65 h60
  text "L11 GND6" at 6070.03,5592.65 h60
  text "CF-004" at 7159.73,5592.65 h60
  text "1.40mil" at 8019.49,5592.65 h60
  text "Dielectric 13" at 6070.03,5472.65 h60
  text "FR4-370HR" at 7159.73,5472.65 h60
  text "3.00mil" at 8019.49,5472.65 h60
  text "3.72" at 8669.33,5472.65 h60
  text "12" at 5660.12,5352.65 h60
  text "L12 PWR3" at 6070.03,5352.65 h60
  text "CF-004" at 7159.73,5352.65 h60
  text "1.40mil" at 8019.49,5352.65 h60
  text "Dielectric 14" at 6070.03,5232.65 h60
  text "FR4-370HR" at 7159.73,5232.65 h60
  text "3.00mil" at 8019.49,5232.65 h60
  text "3.86" at 8669.33,5232.65 h60
  text "13" at 5660.12,5112.65 h60
  text "L13 GND7" at 6070.03,5112.65 h60
  text "CF-004" at 7159.73,5112.65 h60
  text "1.40mil" at 8019.49,5112.65 h60
  text "Dielectric 15" at 6070.03,4992.65 h60
  text "FR4-370HR" at 7159.73,4992.65 h60
  text "3.00mil" at 8019.49,4992.65 h60
  text "3.72" at 8669.33,4992.65 h60
  text "14" at 5660.12,4872.65 h60
  text "L14 PWR4" at 6070.03,4872.65 h60
  text "CF-004" at 7159.73,4872.65 h60
  text "1.40mil" at 8019.49,4872.65 h60
  text "Dielectric 16" at 6070.03,4752.65 h60
  text "FR4-370HR" at 7159.73,4752.65 h60
  text "3.00mil" at 8019.49,4752.65 h60
  text "3.72" at 8669.33,4752.65 h60
  text "15" at 5660.12,4632.65 h60
  text "L15 GND8" at 6070.03,4632.65 h60
  text "CF-004" at 7159.73,4632.65 h60
  text "1.40mil" at 8019.49,4632.65 h60
  text "Dielectric 17" at 6070.03,4512.65 h60
  text "Itera-mt40" at 7159.73,4512.65 h60
  text "6.00mil" at 8019.49,4512.65 h60
  text "3.33" at 8669.33,4512.65 h60
  text "16" at 5660.12,4392.65 h60
  text "Bottom Layer" at 6070.03,4392.65 h60
  text "1.40mil" at 8019.49,4392.65 h60
  text "Bottom Solder" at 6070.03,4272.65 h60
  text "Solder Resist" at 7159.73,4272.65 h60
  text "0.40mil" at 8019.49,4272.65 h60
  text "3.5" at 8669.33,4272.65 h60
  text "Bottom Overlay" at 6070.03,4152.65 h60
  text "Total board thickness:" at 5660.12,4032.65 h60
  text "83.20mil" at 8019.49,4032.65 h60
  text ".Layer_Name" at 587,-858.49 h60
M13 Component Bodies Top:
  text ".Layer_Name" at 587,-858.49 h60
M14 Component Bodies Bottom:
  text ".Layer_Name" at 587,-858.49 h60
M15 Courtyards Top:
  text ".Layer_Name" at 587,-858.49 h60
M16 Courtyards Bottom:
  text ".Layer_Name" at 587,-858.49 h60
Drill Drawing:
  drawing of 152 lines, arcs and shapes, not listed
  text "Symbol" at 5690.42,3467.18 h72
  text "Quantity" at 5990.57,3467.18 h72
  text "Finished Hole Size" at 6322.26,3467.18 h72
  text "Plated" at 6958.12,3467.18 h72
  text "Hole Type" at 7216.92,3467.18 h72
  text "Drill Layer Pair" at 7591.67,3467.18 h72
  text "Hole Tolerance" at 8314.21,3467.18 h72
  text "2" at 5990.57,3343.15 h60
  text "50.00mil (1.270mm)" at 6322.26,3343.15 h60
  text "NPTH" at 6958.12,3343.15 h60
  text "Round" at 7216.92,3343.15 h60
  text "Top Layer - Bottom Layer" at 7591.67,3343.15 h60
  text "2" at 5990.57,3219.12 h60
  text "105.91mil (2.690mm)" at 6322.26,3219.12 h60
  text "NPTH" at 6958.12,3219.12 h60
  text "Round" at 7216.92,3219.12 h60
  text "Top Layer - Bottom Layer" at 7591.67,3219.12 h60
  text "A" at 5665.17,3209.13 h55.12
  text "2" at 5990.57,3095.1 h60
  text "125.98mil (3.200mm)" at 6322.26,3095.1 h60
  text "NPTH" at 6958.12,3095.1 h60
  text "Round" at 7216.92,3095.1 h60
  text "Top Layer - Bottom Layer" at 7591.67,3095.1 h60
  text "119" at 5990.57,2971.07 h60
  text "7.87mil (0.200mm)" at 6322.26,2971.07 h60
  text "PTH" at 6958.12,2971.07 h60
  text "Round" at 7216.92,2971.07 h60
  text "Top Layer - Bottom Layer" at 7591.67,2971.07 h60
  text "1558" at 5990.57,2847.04 h60
  text "8.00mil (0.203mm)" at 6322.26,2847.04 h60
  text "PTH" at 6958.12,2847.04 h60
  text "Round" at 7216.92,2847.04 h60
  text "Top Layer - Bottom Layer" at 7591.67,2847.04 h60
  text "92" at 5990.57,2723.02 h60
  text "10.00mil (0.254mm)" at 6322.26,2723.02 h60
  text "PTH" at 6958.12,2723.02 h60
  text "Round" at 7216.92,2723.02 h60
  text "Top Layer - Bottom Layer" at 7591.67,2723.02 h60
  text "40" at 5990.57,2598.99 h60
  text "12.00mil (0.305mm)" at 6322.26,2598.99 h60
  text "PTH" at 6958.12,2598.99 h60
  text "Round" at 7216.92,2598.99 h60
  text "Top Layer - Bottom Layer" at 7591.67,2598.99 h60
  text "40" at 5990.57,2474.96 h60
  text "12.99mil (0.330mm)" at 6322.26,2474.96 h60
  text "PTH" at 6958.12,2474.96 h60
  text "Round" at 7216.92,2474.96 h60
  text "Top Layer - Bottom Layer" at 7591.67,2474.96 h60
  text "D" at 5665.17,2464.97 h55.12
  text "12" at 5990.57,2350.94 h60
  text "15.00mil (0.381mm)" at 6322.26,2350.94 h60
  text "PTH" at 6958.12,2350.94 h60
  text "Round" at 7216.92,2350.94 h60
  text "Top Layer - Bottom Layer" at 7591.67,2350.94 h60
  text "B" at 5665.17,2340.95 h55.12
  text "8" at 5990.57,2226.91 h60
  text "15.75mil (0.400mm)" at 6322.26,2226.91 h60
  text "PTH" at 6958.12,2226.91 h60
  text "Round" at 7216.92,2226.91 h60
  text "Top Layer - Bottom Layer" at 7591.67,2226.91 h60
  text "57" at 5990.57,2102.88 h60
  text "28.00mil (0.711mm)" at 6322.26,2102.88 h60
  text "PTH" at 6958.12,2102.88 h60
  text "Round" at 7216.92,2102.88 h60
  text "Top Layer - Bottom Layer" at 7591.67,2102.88 h60
  text "F" at 5665.17,2092.89 h55.12
  text "6" at 5990.57,1978.86 h60
  text "40.00mil (1.016mm)" at 6322.26,1978.86 h60
  text "PTH" at 6958.12,1978.86 h60
  text "Round" at 7216.92,1978.86 h60
  text "Top Layer - Bottom Layer" at 7591.67,1978.86 h60
  text "3" at 5990.57,1854.83 h60
  text "42.91mil (1.090mm)" at 6322.26,1854.83 h60
  text "PTH" at 6958.12,1854.83 h60
  text "Round" at 7216.92,1854.83 h60
  text "Top Layer - Bottom Layer" at 7591.67,1854.83 h60
  text "6" at 5990.57,1730.8 h60
  text "47.24mil (1.200mm)" at 6322.26,1730.8 h60
  text "PTH" at 6958.12,1730.8 h60
  text "Round" at 7216.92,1730.8 h60
  text "Top Layer - Bottom Layer" at 7591.67,1730.8 h60
  text "H" at 5665.17,1720.81 h55.12
  text "5" at 5990.57,1606.78 h60
  text "63.00mil (1.600mm)" at 6322.26,1606.78 h60
  text "PTH" at 6958.12,1606.78 h60
  text "Round" at 7216.92,1606.78 h60
  text "Top Layer - Bottom Layer" at 7591.67,1606.78 h60
  text "32" at 5990.57,1482.75 h60
  text "66.93mil (1.700mm)" at 6322.26,1482.75 h60
  text "PTH" at 6958.12,1482.75 h60
  text "Round" at 7216.92,1482.75 h60
  text "Top Layer - Bottom Layer" at 7591.67,1482.75 h60
  text "8" at 5990.57,1358.72 h60
  text "81.00mil (2.057mm)" at 6322.26,1358.72 h60
  text "PTH" at 6958.12,1358.72 h60
  text "Round" at 7216.92,1358.72 h60
  text "Top Layer - Bottom Layer" at 7591.67,1358.72 h60
  text "2" at 5990.57,1234.7 h60
  text "84.00mil (2.134mm)" at 6322.26,1234.7 h60
  text "PTH" at 6958.12,1234.7 h60
  text "Round" at 7216.92,1234.7 h60
  text "Top Layer - Bottom Layer" at 7591.67,1234.7 h60
  text "C" at 5665.17,1224.7 h55.12
  text "2" at 5990.57,1110.67 h60
  text "27.56mil (0.700mm)" at 6322.26,1110.67 h60
  text "PTH" at 6958.12,1110.67 h60
  text "Slot" at 7216.92,1110.67 h60
  text "Top Layer - Bottom Layer" at 7591.67,1110.67 h60
  text "I" at 5674.36,1100.68 h55.12
  text "2" at 5990.57,986.64 h60
  text "29.92mil (0.760mm)" at 6322.26,986.64 h60
  text "PTH" at 6958.12,986.64 h60
  text "Slot" at 7216.92,986.64 h60
  text "Top Layer - Bottom Layer" at 7591.67,986.64 h60
  text "1" at 5990.57,862.62 h60
  text "39.76mil (1.010mm)" at 6322.26,862.62 h60
  text "PTH" at 6958.12,862.62 h60
  text "Slot" at 7216.92,862.62 h60
  text "Top Layer - Bottom Layer" at 7591.67,862.62 h60
  text "1999 Total" at 5990.57,738.59 h60
  text "Slot definitions :" at 5690.42,651.77 h60
  text "Routed Path Length" at 6139.86,651.77 h60
  text "= Calculated from tool start centre position to tool end centre position." at 6678.21,651.77 h60
  text "Hole Length" at 6139.86,602.16 h60
  text "= Routed Path Length + Tool Size = Slot length as defined in the PCB layout" at 6478.91,602.16 h60
  text ".Layer_Name" at 417,-388.49 h60
M17 Embedded Cavity:
  text ".Layer_Name" at 587,-858.49 h60
M18 Embedded Assembly:
  text ".Layer_Name" at 587,-858.49 h60
M19 Embedded Keepout:
  text ".Layer_Name" at 577,-858.49 h60
Drawing:
  lines w10: 1010,-100 1010,1753.98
